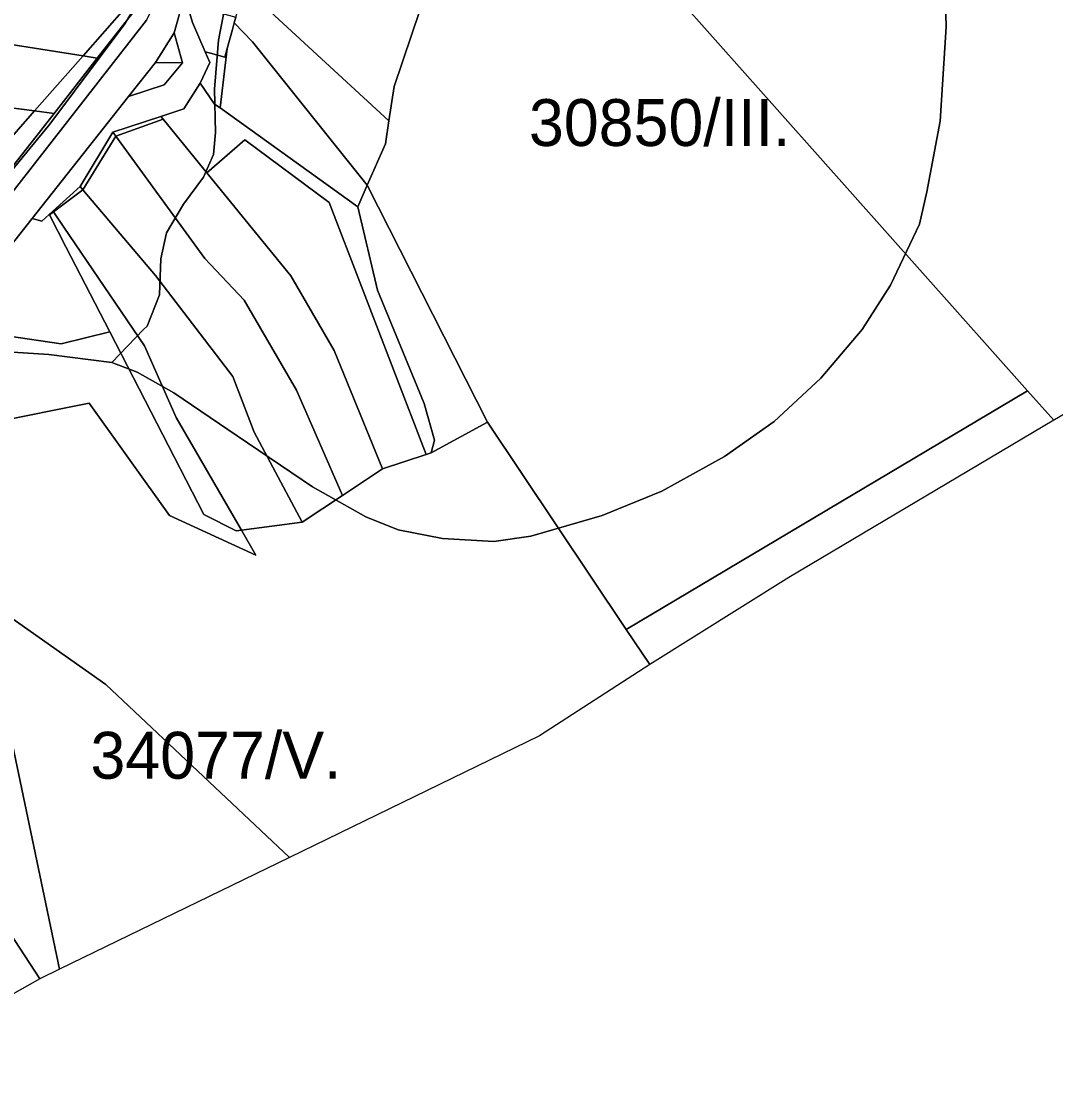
# Model space of a CAD drawing. Extents: x -535894 to -532827, y -1165802 to -1163635.
# Drawn here: x -533891.9 to -533561, y -1165285 to -1164945 of the extents above; entities that cross this region are included whole.
import ezdxf

# ---------------------------------------------------------------- set-up
doc = ezdxf.new("R2010")
doc.units = 0
for name, color, linetype in [('BPEJ_s', 7, 'Continuous'), ('orna_s', 7, 'Continuous'), ('ostatni_s', 7, 'Continuous'), ('sad_s', 7, 'Continuous'), ('trav_porost_s', 7, 'Continuous'), ('voda_s', 7, 'Continuous'), ('zahrada_s', 7, 'Continuous')]:
    doc.layers.add(name, color=color, linetype=linetype)

msp = doc.modelspace()

# ---------------------------------------------------------------- linework, layer by layer
at = {"layer": 'BPEJ_s'}
for points in [[(-534128.66, -1165234.701), (-534052.52, -1165160.48), (-533990.56, -1165093.1), (-533942.78, -1165048.02), (-533910.29, -1165011.39), (-533882.731, -1164977.94), (-533858.68, -1164945.769), (-533840.52, -1164915.19)], [(-533840.52, -1164915.19), (-533858.68, -1164945.769), (-533882.731, -1164977.94), (-533910.29, -1165011.39)], [(-533894.52, -1165050.89), (-533883.051, -1165051.61), (-533862.9, -1165054.24), (-533854.78, -1165057.34), (-533843.07, -1165063.95), (-533822.84, -1165077.65), (-533798.699, -1165094), (-533781.59, -1165103.61), (-533771.32, -1165107.75), (-533757.06, -1165110.541), (-533740.73, -1165111.5), (-533728.87, -1165109.75), (-533706.01, -1165103.14), (-533686.98, -1165095.33), (-533666.909, -1165084.26), (-533650.981, -1165073.11), (-533636.09, -1165059.169), (-533622.875, -1165043.634), (-533613.79, -1165029.47), (-533604.55, -1165009.88), (-533602.16, -1164999.6), (-533597.94, -1164976.91), (-533596.03, -1164946.8), (-533596.75, -1164919.33)], [(-533596.75, -1164919.33), (-533596.03, -1164946.8), (-533597.94, -1164976.91), (-533602.16, -1164999.6), (-533604.55, -1165009.88), (-533613.79, -1165029.47), (-533622.875, -1165043.634), (-533636.09, -1165059.169), (-533650.981, -1165073.11), (-533666.909, -1165084.26), (-533686.98, -1165095.33), (-533706.01, -1165103.14), (-533728.87, -1165109.75), (-533740.73, -1165111.5), (-533757.06, -1165110.541), (-533771.32, -1165107.75), (-533781.59, -1165103.61), (-533798.699, -1165094), (-533822.84, -1165077.65), (-533843.07, -1165063.95), (-533854.78, -1165057.34), (-533862.9, -1165054.24), (-533852.7, -1165043.679), (-533851.59, -1165042.53), (-533847.61, -1165032.5), (-533847.255, -1165021.032), (-533845.38, -1165012.74), (-533839.96, -1165003.51), (-533833.576, -1164994.919), (-533830.33, -1164987.66), (-533829.69, -1164980.571), (-533830.01, -1164966.71), (-533828.81, -1164951.02), (-533825.793, -1164935.576)], [(-533825.793, -1164935.576), (-533828.81, -1164951.02), (-533830.01, -1164966.71), (-533829.69, -1164980.571), (-533830.33, -1164987.66), (-533833.576, -1164994.919), (-533839.96, -1165003.51), (-533845.38, -1165012.74), (-533847.255, -1165021.032), (-533847.61, -1165032.5), (-533851.59, -1165042.53), (-533852.7, -1165043.679), (-533862.9, -1165054.24), (-533883.051, -1165051.61), (-533894.52, -1165050.89)], [(-533510.43, -1165042.58), (-533561.35, -1165072.56), (-533561.52, -1165072.67), (-533646.35, -1165122.98), (-533690.81, -1165150.82), (-533726.09, -1165173.68), (-533806.07, -1165212.59), (-533879.59, -1165248.35), (-533885.93, -1165251.42), (-533928.089, -1165275.274)]]:
    msp.add_lwpolyline(points, dxfattribs=at)
at = {"layer": 'orna_s'}
msp.add_lwpolyline([(-533742.52, -1164866.61), (-533736.23, -1164866.01), (-533737.9, -1164874.36), (-533755.71, -1164908.94), (-533761.58, -1164933.18), (-533772.59, -1164965.85), (-533774.28, -1164976.84), (-533820.25, -1164934.38), (-533804.16, -1164898.7), (-533796.49, -1164887.05), (-533776.21, -1164876.21), (-533758.34, -1164877.03)], close=True, dxfattribs=at)
at = {"layer": 'ostatni_s'}
for points in [[(-533932.96, -1164927.87), (-533906.44, -1164932.7), (-533893.29, -1164935.49), (-533882.11, -1164937.86), (-533879.19, -1164938.15), (-533865.26, -1164939.55), (-533858.16, -1164940.26), (-533872.1, -1164956.08), (-533949.39, -1164943.93), (-533957.74, -1164942.58), (-533951.96, -1164924.41)], [(-534012.88, -1164933.73), (-534002.31, -1164935.43), (-534002.59, -1164936.19), (-533995.11, -1164939.02), (-533994.24, -1164936.72), (-533968.93, -1164940.8), (-533970.51, -1164945.79), (-533967.85, -1164946.68), (-533968.66, -1164949.26), (-533963.29, -1164950.96), (-533962.47, -1164948.39), (-533959.85, -1164949.22), (-533957.74, -1164942.58), (-533949.39, -1164943.93), (-533872.1, -1164956.08), (-533887.6, -1164973.66), (-533934.25, -1164967.65), (-533986.88, -1164958.63), (-534018.61, -1164950.58)], [(-533840.25, -1164939.22), (-533839.74, -1164936.26), (-533838.84, -1164939.32), (-533837.05, -1164945.36), (-533833.05, -1164954.72), (-533831.57, -1164958.17), (-533834.53, -1164964.59), (-533834.67, -1164964.81), (-533839.81, -1164972.99), (-533847.23, -1164975.45), (-533862.51, -1164980.51), (-533873, -1164997.87), (-533881.73, -1165005.74), (-533882.92, -1165006.8), (-533885.29, -1165008.94), (-533888.41, -1165008.1), (-533857.58, -1164969.11), (-533846.11, -1164965.37), (-533840.3, -1164958.31), (-533842.95, -1164948.65)], [(-533838.84, -1164939.32), (-533831.21, -1164941.49), (-533830.64, -1164941.66), (-533823.23, -1164943.69), (-533823.73, -1164945.5), (-533824.3, -1164947.57), (-533825.98, -1164953.67), (-533826.74, -1164956.45), (-533831.37, -1164955.18), (-533833.05, -1164954.72), (-533837.05, -1164945.36)], [(-533855.19, -1164940.56), (-533856.28, -1164942.38), (-533867.55, -1164956.8), (-533872.1, -1164956.08), (-533858.16, -1164940.26)], [(-533842.95, -1164948.65), (-533840.3, -1164958.31), (-533848.9, -1164958.14)], [(-534018.61, -1164950.58), (-533986.88, -1164958.63), (-533934.25, -1164967.65), (-533887.6, -1164973.66), (-533903.09, -1164991.22), (-533954.36, -1164984.01), (-534025.02, -1164969.45)], [(-533872.1, -1164956.08), (-533867.55, -1164956.8), (-533881.35, -1164974.47), (-533887.6, -1164973.66)], [(-533848.9, -1164958.14), (-533840.3, -1164958.31), (-533846.11, -1164965.37), (-533857.58, -1164969.11)], [(-533887.6, -1164973.66), (-533881.35, -1164974.47), (-533895.29, -1164992.32), (-533903.09, -1164991.22)], [(-533882.92, -1165006.8), (-533882.85, -1165006.93), (-533877.59, -1165017.13), (-533863.57, -1165044.37), (-533879.05, -1165048.19), (-533913.9, -1165043.12), (-533923.15, -1165047.3), (-533906.69, -1165031.23), (-533902.3, -1165025.67), (-533888.41, -1165008.1), (-533885.29, -1165008.94)], [(-533881.57, -1165005.98), (-533882.85, -1165006.93), (-533882.92, -1165006.8), (-533881.73, -1165005.74)], [(-533882.85, -1165006.93), (-533881.57, -1165005.98), (-533878.27, -1165010.84), (-533852.39, -1165048.84), (-533842.3, -1165071.83), (-533821.44, -1165107.85), (-533823.1, -1165108.06), (-533833.46, -1165102.84), (-533863.57, -1165044.37), (-533877.59, -1165017.13)], [(-533923.15, -1165047.3), (-533913.9, -1165043.12), (-533879.05, -1165048.19), (-533863.57, -1165044.37), (-533833.46, -1165102.84), (-533823.1, -1165108.06), (-533821.44, -1165107.85), (-533816.78, -1165115.9), (-533844.4, -1165103.16), (-533870.09, -1165067.22), (-533901.06, -1165073.37), (-533921.87, -1165077.16), (-533932.89, -1165078.2), (-533942.64, -1165066.34)]]:
    msp.add_lwpolyline(points, close=True, dxfattribs=at)
for points in [[(-533895.29, -1164992.32), (-533881.35, -1164974.47), (-533867.55, -1164956.8), (-533856.28, -1164942.38)], [(-533851.83, -1164944.65), (-533913.79, -1165024.04)]]:
    msp.add_lwpolyline(points, dxfattribs=at)
at = {"layer": 'sad_s'}
msp.add_lwpolyline([(-533510.43, -1165042.58), (-533561.35, -1165072.56), (-533561.52, -1165072.67), (-533570, -1165063.27), (-533737.9, -1164874.36), (-533736.23, -1164866.01), (-533724, -1164860.16), (-533717.48, -1164860.13), (-533696.31, -1164848.54), (-533670.19, -1164839.35), (-533626.96, -1164831.3), (-533613.25, -1164834.55), (-533603.37, -1164835.56), (-533596.46, -1164833.25), (-533553.28, -1164851.89)], dxfattribs=at)
at = {"layer": 'trav_porost_s'}
for points in [[(-533846.51, -1164976.33), (-533861.56, -1164981.81), (-533862.51, -1164980.51), (-533847.23, -1164975.45)], [(-533861.56, -1164981.81), (-533846.51, -1164976.33), (-533832.53, -1164993.45), (-533805.59, -1165026.46), (-533791.78, -1165050.33), (-533776.32, -1165088.28), (-533789.06, -1165096.75), (-533803.83, -1165063.03), (-533820.54, -1165034.21), (-533833.13, -1165020.87)], [(-533862.51, -1164980.51), (-533861.56, -1164981.81), (-533872.11, -1164998.92), (-533873, -1164997.87)], [(-533872.11, -1164998.92), (-533861.56, -1164981.81), (-533833.13, -1165020.87), (-533820.54, -1165034.21), (-533803.83, -1165063.03), (-533789.06, -1165096.75), (-533801.99, -1165105.35), (-533817.35, -1165076.54), (-533824.2, -1165058.65), (-533848.91, -1165026.4)], [(-533820.39, -1164982.94), (-533793.32, -1165003.01), (-533762.32, -1165083.63), (-533776.32, -1165088.28), (-533791.78, -1165050.33), (-533805.59, -1165026.46), (-533832.53, -1164993.45)], [(-533784.18, -1165004.34), (-533781.22, -1164997.48), (-533742.77, -1165073.32), (-533760.78, -1165083.11), (-533759.69, -1165079.1), (-533762.95, -1165067.3), (-533777.91, -1165031.04)], [(-533872.11, -1164998.92), (-533881.57, -1165005.98), (-533881.73, -1165005.74), (-533873, -1164997.87)], [(-533881.57, -1165005.98), (-533872.11, -1164998.92), (-533848.91, -1165026.4), (-533824.2, -1165058.65), (-533817.35, -1165076.54), (-533801.99, -1165105.35), (-533821.44, -1165107.85), (-533842.3, -1165071.83), (-533852.39, -1165048.84), (-533878.27, -1165010.84)], [(-533903.4, -1165135.17), (-533899.27, -1165133.08), (-533864.82, -1165157.28), (-533806.07, -1165212.59), (-533879.59, -1165248.35)], [(-533962.19, -1165187.57), (-533942.82, -1165162.9), (-533914.6, -1165207.64), (-533885.93, -1165251.42), (-533945.33, -1165285.03), (-533992.77, -1165214.76), (-533989.71, -1165212.03)]]:
    msp.add_lwpolyline(points, close=True, dxfattribs=at)
for points in [[(-533901.06, -1165073.37), (-533870.09, -1165067.22), (-533844.4, -1165103.16), (-533816.78, -1165115.9), (-533821.44, -1165107.85), (-533801.99, -1165105.35), (-533789.06, -1165096.75), (-533776.32, -1165088.28), (-533762.32, -1165083.63), (-533760.78, -1165083.11), (-533742.77, -1165073.32), (-533698.37, -1165139.6), (-533690.81, -1165150.82), (-533726.09, -1165173.68), (-533806.07, -1165212.59), (-533864.82, -1165157.28), (-533899.27, -1165133.08)], [(-533903.4, -1165135.17), (-533879.59, -1165248.35), (-533885.93, -1165251.42), (-533914.6, -1165207.64)]]:
    msp.add_lwpolyline(points, dxfattribs=at)
at = {"layer": 'voda_s'}
for points in [[(-533913.79, -1165024.04), (-533851.83, -1164944.65), (-533849.69, -1164940.46), (-533843.98, -1164906.47), (-533838.18, -1164893.83), (-533831.54, -1164880.79), (-533827.73, -1164876.4), (-533824.38, -1164874.44), (-533814.12, -1164868.44), (-533807.19, -1164864.79), (-533772.11, -1164858.69), (-533727.16, -1164854.1), (-533726.9, -1164854), (-533723.4, -1164852.55), (-533719.59, -1164850.96), (-533704.29, -1164842.98), (-533700.79, -1164841.16), (-533699.02, -1164840.23), (-533671.59, -1164831.22), (-533632.04, -1164823.51)], [(-533840.25, -1164939.22), (-533842.95, -1164948.65), (-533848.9, -1164958.14), (-533857.58, -1164969.11), (-533888.41, -1165008.1), (-533902.3, -1165025.67)]]:
    msp.add_lwpolyline(points, dxfattribs=at)
at = {"layer": 'zahrada_s'}
for points in [[(-533755.71, -1164908.94), (-533737.9, -1164874.36), (-533570, -1165063.27), (-533698.37, -1165139.6), (-533742.77, -1165073.32), (-533781.22, -1164997.48), (-533775.32, -1164984.22), (-533774.28, -1164976.84), (-533772.59, -1164965.85), (-533761.58, -1164933.18)], [(-533821.32, -1164936.75), (-533820.25, -1164934.38), (-533774.28, -1164976.84), (-533775.32, -1164984.22), (-533781.22, -1164997.48), (-533817.86, -1164951.61), (-533823.73, -1164945.5), (-533823.23, -1164943.69)], [(-533824.3, -1164947.57), (-533823.73, -1164945.5), (-533817.86, -1164951.61), (-533781.22, -1164997.48), (-533784.18, -1165004.34), (-533828.25, -1164972.65), (-533825.98, -1164953.67)], [(-533833.05, -1164954.72), (-533831.37, -1164955.18), (-533826.74, -1164956.45), (-533825.98, -1164953.67), (-533828.25, -1164972.65), (-533830.03, -1164971.49), (-533834.67, -1164964.81), (-533834.53, -1164964.59), (-533831.57, -1164958.17)], [(-533834.67, -1164964.81), (-533830.03, -1164971.49), (-533828.25, -1164972.65), (-533784.18, -1165004.34), (-533777.91, -1165031.04), (-533762.95, -1165067.3), (-533759.69, -1165079.1), (-533760.78, -1165083.11), (-533762.32, -1165083.63), (-533793.32, -1165003.01), (-533820.39, -1164982.94), (-533832.53, -1164993.45), (-533846.51, -1164976.33), (-533847.23, -1164975.45), (-533839.81, -1164972.99)], [(-533570, -1165063.27), (-533561.52, -1165072.67), (-533646.35, -1165122.98), (-533690.81, -1165150.82), (-533698.37, -1165139.6)]]:
    msp.add_lwpolyline(points, close=True, dxfattribs=at)

# ---------------------------------------------------------------- texts
at = {"layer": 'BPEJ_s'}
for s, p in [('30850/III.', (-533729.465, -1164984.907)), ('34077/V.', (-533869.713, -1165187.4))]:
    msp.add_text(s, height=15, dxfattribs=at).set_placement(p)

doc.saveas('drawing.dxf')
